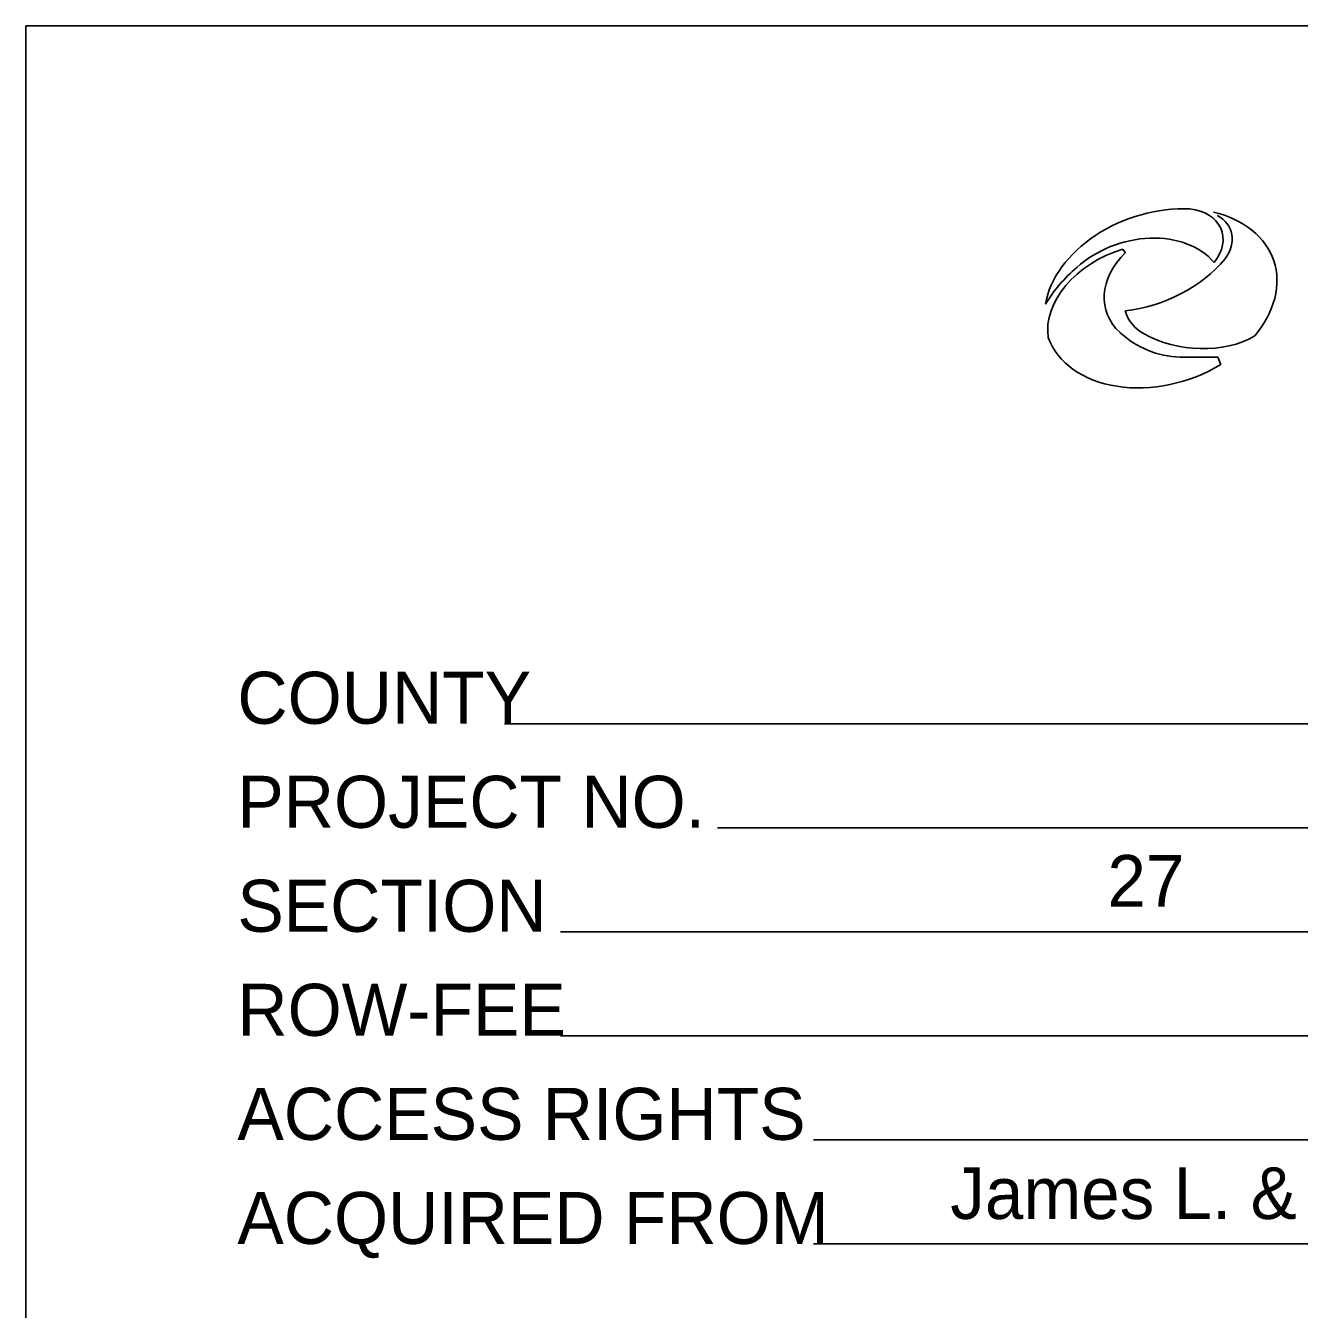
# Model space of a CAD drawing. Extents: x 23379288 to 23380138, y 6801100 to 6802500.
# Drawn here: x 23379287.8 to 23379532.6, y 6802253.7 to 6802500.5 of the extents above; entities that cross this region are included whole.
import ezdxf

# ---------------------------------------------------------------- set-up
doc = ezdxf.new("R2010")
doc.units = 0
for name, color, linetype in [('DisPlatCells', 7, 'Continuous'), ('DisPlatData', 7, 'Continuous'), ('Level 60', 7, 'Continuous')]:
    doc.layers.add(name, color=color, linetype=linetype)

msp = doc.modelspace()

# ---------------------------------------------------------------- linework, layer by layer
at = {"layer": 'DisPlatCells'}
for p, q in [((23379379.82, 6802366.26), (23379763.49, 6802366.26)), ((23379420.76, 6802346.26), (23379813.49, 6802346.26)), ((23379390.56, 6802326.27), (23379603.49, 6802326.27)), ((23379390.56, 6802306.27), (23379580.39, 6802306.27)), ((23379439.22, 6802286.27), (23380063.5, 6802286.27)), ((23379439.22, 6802266.26), (23380063.5, 6802266.26))]:
    msp.add_line(p, q, dxfattribs=at)
at = {"layer": 'DisPlatData'}
for p, q in [((23379499.16, 6802456.88), (23379498.71, 6802457.52)), ((23379518.3, 6802455.6), (23379518.29, 6802455.6)), ((23379516.95, 6802436.76), (23379509.69, 6802436.76)), ((23379517.52, 6802435.33), (23379516.95, 6802436.77))]:
    msp.add_line(p, q, dxfattribs=at)
for centre, radius, start, end in [((23379508.9, 6802431.61), 29.4, 130.4073, 148.6116), ((23379506.15, 6802447.74), 7.33, 196.6637, 241.4253), ((23379510.26, 6802454.66), 17.91, 227.4121, 268.1853)]:
    msp.add_arc(centre, radius, start, end, dxfattribs=at)
for centre, major_axis, ratio, start_param, end_param in [((23379505.96, 6802448.05), (21.75, 7.18), 0.719533, 1.083877, 2.776754), ((23379508.84, 6802458.1), (8.86, 2.92), 0.742604, 5.415668, 7.30889), ((23379505.96, 6802448.05), (21.75, 7.18), 0.719533, 5.420409, 7.150486), ((23379510.48, 6802458.02), (9, 2.97), 0.704235, 5.49205, 6.868046), ((23379501.59, 6802445.72), (16.52, 6.05), 0.758843, 0.277596, 2.054956), ((23379502.35, 6802444.67), (17.62, 5.82), 0.719533, 1.539733, 3.015069), ((23379511.43, 6802450.52), (15.94, 4.97), 0.719533, 2.199069, 3.541651), ((23379500.09, 6802462.65), (21.75, 7.18), 0.719533, 4.436236, 5.430881), ((23379512.62, 6802449.27), (16.25, -1.78), 0.661581, 4.12595, 5.561254), ((23379505.96, 6802448.05), (21.75, 7.18), 0.719533, 3.165191, 5.022008)]:
    msp.add_ellipse(centre, major_axis=major_axis, ratio=ratio, start_param=start_param, end_param=end_param, dxfattribs=at)
at = {"layer": 'Level 60'}
for p, q in [((23379287.77, 6802500.47), (23380137.79, 6802500.47)), ((23379287.77, 6801100.45), (23379287.77, 6802500.47))]:
    msp.add_line(p, q, dxfattribs=at)

# ---------------------------------------------------------------- texts
at = {"layer": 'DisPlatCells'}
for s, height, p in [('COUNTY', 10, (23379328.47, 6802366.26)), ('PROJECT NO.', 10.0002, (23379328.47, 6802346.26)), ('SECTION', 10, (23379328.47, 6802326.27)), ('ROW-FEE', 10, (23379328.47, 6802306.27)), ('ACCESS RIGHTS', 10.0002, (23379328.47, 6802286.27)), ('ACQUIRED FROM', 10.0002, (23379328.47, 6802266.26))]:
    msp.add_text(s, height=height, dxfattribs=at).set_placement(p)
at = {"layer": 'DisPlatData'}
for s, height, p in [('27', 9.96, (23379495.72, 6802331.07)), ('James L. & Vickie A. Striegel', 9.9602, (23379465.51, 6802271.06))]:
    msp.add_text(s, height=height, dxfattribs=at).set_placement(p)

doc.saveas('drawing.dxf')
